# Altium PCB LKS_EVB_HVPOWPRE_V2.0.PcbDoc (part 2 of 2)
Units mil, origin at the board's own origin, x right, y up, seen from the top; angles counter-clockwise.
Board outline 6702.91 x 4340.71 mil, 2 copper layers (Top Layer, Bottom Layer); 149 components, 99 nets, 418 pads, 120 vias.
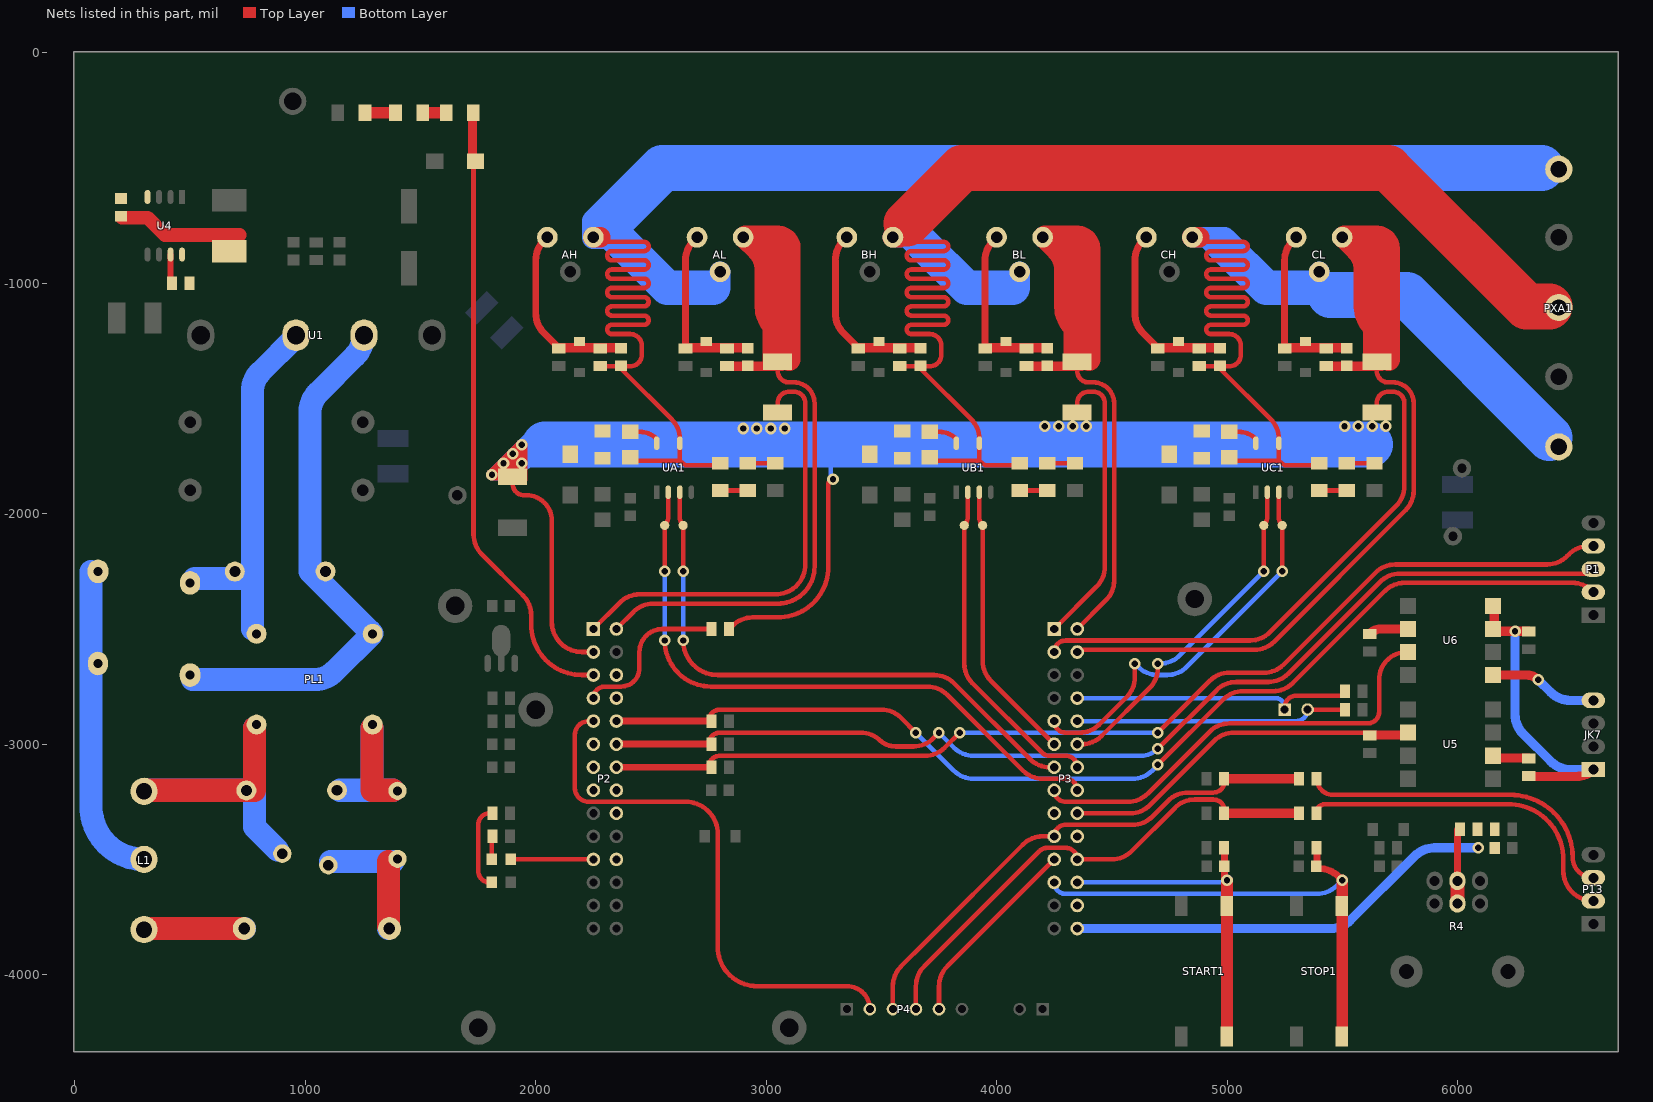
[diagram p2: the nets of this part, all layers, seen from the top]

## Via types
v1: diameter 50, hole 28, Top Layer to Bottom Layer, 120 vias

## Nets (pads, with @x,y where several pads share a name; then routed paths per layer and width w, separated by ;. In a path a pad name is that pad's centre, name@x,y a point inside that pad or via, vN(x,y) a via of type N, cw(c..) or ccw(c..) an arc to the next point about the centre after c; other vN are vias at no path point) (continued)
HA: P1.4 P2.21 R53.1 | length 4604.3
  Top Layer w20: R53.1@2750,-3100 cw(c2800,-3100) 2760,-3070 cw(c2800,-3100) 2770,-3060 cw(c2800,-3100) 2800,-3050 3690,-3050 ccw(c3690,-2929.29) 3775.36,-3014.64 v1(3840,-2950) ; v1(4700,-2950) 4924.64,-2725.36 cw(c5010,-2810.71) 5010,-2690 5160,-2690 ccw(c5160,-2569.29) 5245.36,-2654.64 5644.64,-2255.36 cw(c5730,-2340.71) 5730,-2220 6390,-2220 ccw(c6390,-2099.29) 6475.36,-2184.64 6484.64,-2175.36 cw(c6570,-2260.71) 6570,-2140 P1.4@6590,-2140
  Top Layer w30: P2.21@2350,-3100 R53.1@2750,-3100
  Bottom Layer w20: v1@3850,-2950 v1(4700,-2950)
HALL_A: P2.6
HALL_B: P2.7
HALL_C: P2.8
HB: P1.3 P2.20 R52.1 | length 4654.5
  Top Layer w20: R52.1@2750,-3000 cw(c2800,-3000) 2760,-2970 cw(c2800,-3000) 2770,-2960 cw(c2800,-3000) 2800,-2950 3410,-2950 cw(c3410,-3070.71) 3495.36,-2985.36 ; 3490,-2980 ccw(c3562.43,-2907.57) 3562.43,-3010 3640,-3010 ccw(c3640,-2889.29) 3725.36,-2974.64 v1(3750,-2950) ; v1(4700,-3020) 4954.64,-2765.36 cw(c5040,-2850.71) 5040,-2730 5180,-2730 ccw(c5180,-2609.29) 5265.36,-2694.64 5664.64,-2295.36 cw(c5750,-2380.71) 5750,-2260 P1.3@6590,-2260
  Top Layer w30: P2.20@2350,-3000 R52.1@2750,-3000
  Bottom Layer w20: v1(3750,-2950) 3814.64,-3014.64 ccw(c3900,-2929.29) 3900,-3050 4627.57,-3050 ccw(c4627.57,-2947.57) v1(4700,-3020)
HC: P1.2 P2.19 R51.1 | length 4718.5
  Top Layer w20: R51.1@2750,-2900 cw(c2800,-2900) 2760,-2870 cw(c2800,-2900) 2770,-2860 cw(c2800,-2900) 2800,-2850 3500,-2850 cw(c3500,-2970.71) 3585.36,-2885.36 v1(3650,-2950) ; v1(4700,-3090) 4984.64,-2805.36 cw(c5070,-2890.71) 5070,-2770 5200,-2770 ccw(c5200,-2649.29) 5285.36,-2734.64 5684.64,-2335.36 cw(c5770,-2420.71) 5770,-2300 6500,-2300 cw(c6500,-2420.71) P1.2@6585.36,-2335.36
  Top Layer w30: P2.19@2350,-2900 R51.1@2750,-2900
  Bottom Layer w20: v1(3650,-2950) 3814.64,-3114.64 ccw(c3900,-3029.29) 3900,-3150 4590,-3150 ccw(c4590,-3029.29) 4675.36,-3114.64 v1(4700,-3090)
HGND: JK7.4 U6.5 | length 467.4
  Top Layer w40: U6.5@6160,-2700 6301.72,-2700 cw(c6301.72,-2768.28) v1(6350,-2720)
  Bottom Layer w40: v1(6350,-2720) 6404.64,-2774.64 ccw(c6490,-2689.29) 6490,-2810 JK7.4@6590,-2810
IIC_CLK: P3.19 P6.2 R5.1 | length 1188.9
  Top Layer w20: P6.2@5350,-2850 R5.1@5510,-2850
  Bottom Layer w20: P3.19@4350,-2900 5300,-2900 ; 5300.25,-2899.75 cw(c5300,-2899.75) 5300,-2900 ; P6.2@5350,-2850 cw(c5300,-2850) 5300,-2900
IIC_DA: P3.18 P6.1 R6.1 | length 1236.4
  Top Layer w20: P6.1@5250,-2850 5250,-2840 cw(c5300,-2840) 5300,-2790 R6.1@5515,-2790
  Bottom Layer w20: P3.18@4350,-2800 5210,-2800 cw(c5210,-2840) 5250,-2840 P6.1@5250,-2850
L: F1.1 L1.3 | length 855
  Top Layer w100: L1.3@310,-3800 F1.1@730,-3800
  Bottom Layer w100: L1.3@300,-3800 F1.1@735,-3800
N: CX1.1 L1.1 PL1.1 RV1.1 | length 1761.4
  Top Layer w100: L1.1@300,-3200 780,-3200 PL1.1@780,-2930
  Bottom Layer w100: L1.1@300,-3200 CX1.1@740,-3200 ; PL1.1@780,-2930 780,-3360 RV1.1@880,-3460
NetCX4_1: CX4.1 U4.4
NetD4_K: D4.K R3P.1
NetD11_K: D11.K R1P.1
NetD21_K: D21.K R2P.1
NetDA2_1: AL.1 C11.1 DA2.1 K-A1.1 R31.1 | length 755.5
  Top Layer w30: K-A1.1@2650,-1280 2650,-900 cw(c2770.71,-900) 2685.36,-814.64 AL.1@2700,-800
  Top Layer w40: K-A1.1@2650,-1280 C11.1@2910,-1280
NetDA5_1: C24.1 CH.1 DA5.1 K+C1.2 R50.2 | length 801.7
  Top Layer w30: CH.1@4650,-800 4635.36,-814.64 ccw(c4720.71,-900) 4600,-900 4600,-1130 ccw(c4720.71,-1130) 4635.36,-1215.36 K+C1.2@4700,-1280
  Top Layer w40: K+C1.2@4700,-1280 C24.1@4970,-1280
NetDA6_1: C34.1 CL.1 DA6.1 K_C1.1 R63.1 | length 755.5
  Top Layer w30: K_C1.1@5250,-1280 5250,-900 cw(c5370.71,-900) 5285.36,-814.64 CL.1@5300,-800
  Top Layer w40: K_C1.1@5250,-1280 C34.1@5510,-1280
NetF1_2: F1.2 R26.2 RV1.2 | length 840
  Top Layer w100: F1.2@1360,-3790 1360,-3510
  Bottom Layer w100: RV1.2@1110,-3510 R26.2@1380,-3510 ; F1.2@1360,-3800 1360,-3510
NetK+A1_2: AH.1 C7.1 DA1.1 K+A1.2 R21.2 | length 801.7
  Top Layer w30: AH.1@2050,-800 2035.36,-814.64 ccw(c2120.71,-900) 2000,-900 2000,-1130 ccw(c2120.71,-1130) 2035.36,-1215.36 K+A1.2@2100,-1280
  Top Layer w40: K+A1.2@2100,-1280 C7.1@2370,-1280
NetK+B1_2: BH.1 C16.1 DA3.1 K+B1.2 R39.2 | length 801.7
  Top Layer w30: BH.1@3350,-800 3335.36,-814.64 ccw(c3420.71,-900) 3300,-900 3300,-1130 ccw(c3420.71,-1130) 3335.36,-1215.36 K+B1.2@3400,-1280
  Top Layer w40: K+B1.2@3400,-1280 C16.1@3670,-1280
NetK_B1_1: BL.1 C20.1 DA4.1 K_B1.1 R45.1 | length 755.5
  Top Layer w30: K_B1.1@3950,-1280 3950,-900 cw(c4070.71,-900) 3985.36,-814.64 BL.1@4000,-800
  Top Layer w40: K_B1.1@3950,-1280 C20.1@4210,-1280
NetLED3_1: LED3.1 R0.1 | length 99
  Top Layer w20: LED3.1@1809,-3500 R0.1@1809,-3401
NetLED_POWER_1: LED_POWER.1 R65.2 | length 376.1
  Top Layer w20: LED_POWER.1@1809,-3600 1800,-3600 cw(c1800,-3550) 1750,-3550 1750,-3350 cw(c1800,-3350) 1800,-3300 R65.2@1810,-3300
NetPL1_2: CX6.1 CY1.2 PL1.2 U1.1 | length 1583.5
  Bottom Layer w100: CY1.2@520,-2280 760,-2280 ; PL1.2@770,-2500 770,-1470 cw(c890.71,-1470) 805.36,-1384.64 U1.1@960,-1230
NetPL1_3: CX6.2 CY2.1 PL1.3 U1.3 | length 2340.2
  Bottom Layer w100: CY2.1@510,-2720 1040,-2720 ccw(c1040,-2599.29) 1125.36,-2684.64 PL1.3@1290,-2520 ; U1.3@1250,-1220 1250,-1230 cw(c1129.29,-1230) 1214.64,-1315.36 1055.36,-1474.64 ccw(c1140.71,-1560) 1020,-1560 1020,-2250 PL1.3@1280,-2510
NetR1_2: R1.2 R23.1 | length 120
  Top Layer w20: R23.1@2800,-1899.06 R1.2@2920,-1899.06
NetR1P_2: CAH1.1 R1P.2 UA1.8 | length 141.8
  Top Layer w20: CAH1.1@2410,-1644.88 2452.29,-1644.88 cw(c2452.29,-1747.71) 2505.96,-1660 cw(c2452.29,-1747.71) 2524.97,-1674.97 UA1.8@2525,-1693.7
NetR2_2: R2.2 R24.1 | length 120
  Top Layer w20: R24.1@4100,-1899.06 R2.2@4220,-1899.06
NetR2P_2: CBH1.1 R2P.2 UB1.8 | length 141.7
  Top Layer w20: CBH1.1@3710,-1644.88 3752.29,-1644.88 cw(c3752.29,-1747.71) 3805.96,-1660 cw(c3752.29,-1747.71) 3824.97,-1674.97 UB1.8@3825,-1693.7
NetR3_2: R3.2 R25.1 | length 120
  Top Layer w20: R25.1@5400,-1899.06 R3.2@5520,-1899.06
NetR3P_2: CCH1.1 R3P.2 UC1.8 | length 141.7
  Top Layer w20: CCH1.1@5010,-1644.88 5052.29,-1644.88 cw(c5052.29,-1747.71) 5105.96,-1660 cw(c5052.29,-1747.71) 5124.97,-1674.97 UC1.8@5125,-1693.7
NetR9_2: P13.2 R9.2 | length 1499.7
  Top Layer w20: R9.2@5380,-3310 cw(c5430,-3310) 5430,-3260 6220,-3260 cw(c6220,-3500) 6460,-3500 6460,-3550 ccw(c6590,-3550) P13.2@6590,-3680
NetR12_2: P13.3 R12.2 | length 1445.4
  Top Layer w20: R12.2@5390,-3150 ccw(c5460,-3150) 5460,-3220 6230,-3220 cw(c6230,-3490) 6500,-3490 ccw(c6590,-3490) P13.3@6590,-3580
NetR22_2: R22.2 R74.1 | length 120
  Top Layer w50: R22.2@1265,-260 R74.1@1385,-260
NetR26_1: CX1.2 PL1.4 R26.1 | length 860
  Top Layer w100: PL1.4@1290,-2930 1290,-3200 R26.1@1380,-3200
  Bottom Layer w100: CX1.2@1150,-3200 R26.1@1380,-3200 ; 1290,-3200 PL1.4@1290,-2930
NetR27_1: R27.1 U6.2 | length 165.3
  Top Layer w40: R27.1@5620,-2520 cw(c5668.28,-2568.28) 5668.28,-2500 U6.2@5780,-2500
NetR29_2: R29.2 U5.2 | length 150
  Top Layer w40: U5.2@6160,-3060 R29.2@6310,-3060
NetR55_2: R1.1 R55.2 | length 120
  Top Layer w20: R1.1@2920,-1780.94 R55.2@3040,-1780.94
NetR59_2: R2.1 R59.2 | length 120
  Top Layer w20: R2.1@4220,-1780.94 R59.2@4340,-1780.94
NetR61_2: R3.1 R61.2 | length 120
  Top Layer w20: R3.1@5520,-1780.94 R61.2@5640,-1780.94
NetR74_2: R74.2 R75.1 | length 100
  Top Layer w50: R74.2@1510,-260 R75.1@1610,-260
NetRX3_1: RX3.1 U4.7 | length 125
  Top Layer w25: RX3.1@415,-1000 U4.7@415,-875
NetRX3_2: CX4.2 L11.1 RX3.2 U4.8 | length 541.1
  Top Layer w60: CX4.2@205,-715 315,-715 390,-790 715,-790
NRST: P2.23
OC: P2.4 R8.2 | length 711.3
  Top Layer w20: P2.4@2250,-2800 cw(c2300,-2800) 2300,-2750 2370,-2750 ccw(c2370,-2670) 2450,-2670 2450,-2600 cw(c2550,-2600) 2550,-2500 R8.2@2760,-2500
P0.0: P2.22
P0.3: LED3.2 P2.11 | length 359
  Top Layer w20: LED3.2@1891,-3500 P2.11@2250,-3500
P0.4: P3.27
P1.3: P3.24
P2.1: P2.18
P2.7: P3.9
P2.10: P2.17
P3.2: P2.25
PE: CY1.1 CY2.2 L1.2 | length 1381.3
  Bottom Layer w100: CY1.1@70,-2250 70,-3270 ccw(c300,-3270) L1.2@300,-3500
RXD0/SPI_D1: P3.25 P4.4 R01.1 R9.1 | length 2191.5
  Top Layer w20: P4.4@3650,-4150 3650,-4050 cw(c3770.71,-4050) 3685.36,-3964.64 3790,-3860 ; 3785.36,-3864.64 4185.86,-3464.14 cw(c4220,-3498.28) 4220,-3450 4300,-3450 cw(c4300,-3500) P3.25@4350,-3500 4500,-3500 ccw(c4500,-3379.29) 4585.36,-3464.64 4774.64,-3275.36 cw(c4860,-3360.71) 4860,-3240 4940,-3240 cw(c4940,-3290) 4983.1,-3264.65 cw(c4940,-3290) R01.1@4990,-3290
  Top Layer w40: R01.1@4990,-3300 R9.1@5310,-3300
RXD1: P3.23 R28.1 U5.6 | length 1564.6
  Top Layer w20: P3.23@4350,-3300 4580,-3300 ccw(c4580,-3179.29) 4665.36,-3264.64 4944.64,-2985.36 cw(c5030,-3070.71) 5030,-2950 R28.1@5620,-2950
  Top Layer w40: R28.1@5620,-2960 U5.6@5780,-2960
SHUNT: P2.1 P2.2 P3.1 P3.2 R8.1 R15.2 R16.2 R17.2 R69.1 | length 12858.5
  Top Layer w20: R69.1@1900,-1840 1900,-1870 ccw(c1950,-1870) 1950,-1920 1960,-1920 cw(c1960,-2030) 2070,-2030 2070,-2470 ccw(c2200,-2470) 2200,-2600 P2.2@2250,-2600 ; P2.1@2250,-2500 2364.64,-2385.36 cw(c2450,-2470.71) 2450,-2350 3040,-2350 ccw(c3040,-2220) 3170,-2220 3170,-1520 ccw(c3120,-1520) 3120,-1470 3100,-1470 ccw(c3100,-1520) 3050,-1520 R15.2@3050,-1550 ; R8.1@2840,-2500 2854.64,-2485.36 cw(c2940,-2570.71) 2940,-2450 3060,-2450 ; 3050,-2450 ccw(c3050,-2230) 3270,-2230 3270,-1874.14 cw(c3304.14,-1874.14) v1@3280,-1850 ; P3.2@4250,-2600 cw(c4300,-2600) 4300,-2550 5100,-2550 ccw(c5100,-2429.29) 5185.36,-2514.64 5734.64,-1965.36 ccw(c5649.29,-1880) 5770,-1880 5770,-1520 ccw(c5720,-1520) 5720,-1470 5700,-1470 ccw(c5700,-1520) 5650,-1520 R17.2@5650,-1550 ; P3.1@4250,-2500 4434.64,-2315.36 ccw(c4349.29,-2230) 4470,-2230 4470,-1520 ; R16.2@4350,-1550 4350,-1520 ; 4350,-1520 cw(c4400,-1520) 4400,-1470 ; 4350,-1520 cw(c4400,-1520) 4400,-1470 ; 4400,-1470 4420,-1470 ; 4400,-1470 4420,-1470 ; 4420,-1470 cw(c4420,-1520) 4470,-1520 ; 4420,-1470 cw(c4420,-1520) 4470,-1520
  Top Layer w50: R69.1@1870,-1820 v1@1930,-1760 ; R69.1@1930,-1830 v1(1810,-1830) v1(1940,-1700) R69.1@1940,-1850
  Bottom Layer w20: v1@3280,-1850 3280,-1778.28
  Bottom Layer w40: v1@1960,-1780 2060,-1780
  Bottom Layer w50: 1880,-1820 1960,-1740 ; v1@1960,-1780 1910,-1830 v1(1810,-1830) 1990,-1650
  Bottom Layer w200: 2040,-1700 2370,-1700 ; 2110,-1700 5620,-1700
  other v1: 3290,-1850 1860,-1780 1940,-1780 1900,-1740 2900,-1630 2960,-1630 3020,-1630 3080,-1630 4210,-1620 4270,-1620 4330,-1620 4390,-1620 5510,-1620 5570,-1620 5630,-1620 5690,-1620
SHUNT_U: AL.3 C11.2 P2.15 R15.1 R31.2 | length 3794
  Top Layer w20: P2.15@2350,-2500 2424.64,-2425.36 cw(c2510,-2510.71) 2510,-2390 ; 2500,-2390 3050,-2390 ccw(c3050,-2230) 3210,-2230 3210,-1520 ccw(c3120,-1520) 3120,-1430 3100,-1430 cw(c3100,-1380) 3050,-1380 R15.1@3050,-1339.76
  Top Layer w40: R31.2@2830,-1360 R15.1@3070,-1360
  Top Layer w50: AL.3@2900,-800 AL.3@2914.64,-814.64
  Top Layer w100: R15.1@3035,-1331 3035,-1195 ; 3035.36,-1185.36 cw(c3120.71,-1100) 3000,-1100 3000,-940 ccw(c2879.29,-940) 2964.64,-854.64 2910,-800 3050,-800 cw(c3050,-850) 3100,-850 R15.1@3100,-1330 ; 3040,-1140 3040,-860
SHUNT_V: BL.3 C20.2 P3.15 R16.1 R45.2 | length 3178.4
  Top Layer w20: P3.15@4350,-2500 4474.64,-2375.36 ccw(c4389.29,-2290) 4510,-2290 4510,-1520 ccw(c4420,-1520) 4420,-1430 4400,-1430 cw(c4400,-1380) 4350,-1380 R16.1@4350,-1339.76
  Top Layer w40: R45.2@4130,-1360 R16.1@4370,-1360
  Top Layer w50: BL.3@4200,-800 BL.3@4214.64,-814.64
  Top Layer w100: 4335.36,-1185.36 cw(c4420.71,-1100) 4300,-1100 4300,-940 ccw(c4179.29,-940) 4264.64,-854.64 4210,-800 4350,-800 cw(c4350,-850) 4400,-850 R16.1@4400,-1330 ; R16.1@4340,-1331 4340,-1140 4340,-860
SHUNT_W: C34.2 CL.3 P3.16 R17.1 R63.2 | length 4261
  Top Layer w20: P3.16@4350,-2590 5120,-2590 ccw(c5120,-2469.29) 5205.36,-2554.64 5774.64,-1985.36 ccw(c5689.29,-1900) 5810,-1900 5810,-1520 ccw(c5720,-1520) 5720,-1430 5700,-1430 cw(c5700,-1380) 5650,-1380 R17.1@5650,-1339.76
  Top Layer w40: R63.2@5430,-1360 R17.1@5670,-1360
  Top Layer w50: CL.3@5500,-800 CL.3@5514.64,-814.64
  Top Layer w100: 5635.36,-1185.36 cw(c5720.71,-1100) 5600,-1100 5600,-940 ccw(c5479.29,-940) 5564.64,-854.64 5510,-800 5650,-800 cw(c5650,-850) 5700,-850 R17.1@5700,-1330 ; R17.1@5640,-1330 5640,-1160 ; 5640,-1140 5640,-860
SPI_CLK: P3.11 P4.5 | length 858.5
  Top Layer w20: P4.5@3750,-4150 3750,-4050 cw(c3870.71,-4050) 3785.36,-3964.64 3890,-3860 ; 3885.36,-3864.64 P3.11@4250,-3500
SPI_CS: P2.5 P4.2 | length 2382.5
  Top Layer w20: P2.5@2250,-2900 2230,-2900 ccw(c2230,-2960) 2170,-2960 2170,-3190 ccw(c2230,-3190) 2230,-3250 2400,-3250 2650,-3250 cw(c2650,-3390) 2790,-3390 2790,-3880 ccw(c2960,-3880) 2960,-4050 3350,-4050 cw(c3350,-4150) P4.2@3450,-4150
SPIN: C19.2 P3.28 R42.2 R43.2 | length 1874.6
  Bottom Layer w40: P3.28@4350,-3800 5450,-3800 ccw(c5450,-3679.29) 5535.36,-3764.64 5814.64,-3485.36 cw(c5900,-3570.71) 5900,-3450 v1(6090,-3450)
START1: C311.2 P3.26 R7.2 START1.2 START1.4 | length 1486.8
  Top Layer w30: v1@4990,-3590 R7.2@4990,-3440
  Top Layer w50: START1.2@5000,-4270 v1(5000,-3590)
  Bottom Layer w20: P3.26@4350,-3600 v1@4980,-3600 ; 4975.86,-3600 ccw(c4975.86,-3565.86) v1(5000,-3590)
STOP1: C2.2 P3.12 R13.2 STOP1.2 STOP1.4 | length 2173
  Top Layer w30: C2.2@5390,-3540 R13.2@5390,-3440 ; C2.2@5400,-3540 cw(c5400,-3660.71) v1@5485.36,-3575.36
  Top Layer w50: STOP1.2@5500,-4270 v1(5500,-3590)
  Bottom Layer w20: P3.12@4250,-3600 ccw(c4300,-3600) 4300,-3650 5390,-3650 ccw(c5390,-3529.29) 5475.36,-3614.64 v1(5500,-3590)
TXD0/SPI_D2: P3.10 P4.3 R02.1 R12.1 | length 2259.4
  Top Layer w20: P4.3@3550,-4150 3550,-4050 cw(c3670.71,-4050) 3585.36,-3964.64 3690,-3860 ; 3685.36,-3864.64 4114.64,-3435.36 cw(c4200,-3520.71) 4200,-3400 P3.10@4250,-3400 cw(c4300,-3400) 4300,-3350 4590,-3350 ccw(c4590,-3229.29) 4675.36,-3314.64 4744.64,-3245.36 cw(c4830,-3330.71) 4830,-3210 4940,-3210 ccw(c4940,-3160) 4983.1,-3185.35 ccw(c4940,-3160) R02.1@4990,-3160
  Top Layer w40: R02.1@4990,-3150 R12.1@5310,-3150
TXD1: P3.8 U6.3 | length 1926
  Top Layer w20: P3.8@4250,-3200 ccw(c4300,-3200) 4300,-3250 4570,-3250 ccw(c4570,-3129.29) 4655.36,-3214.64 4924.64,-2945.36 cw(c5010,-3030.71) 5010,-2910 5610,-2910 ccw(c5610,-2860) 5660,-2860 5660,-2720 cw(c5780,-2720) U6.3@5780,-2600
U_N: P3.7 UA1.3 UN.1 | length 2506.3
  Top Layer w20: UA1.3@2625,-1906.3 2625,-2015.13 ccw(c2674.87,-2015.13) UN.1@2639.61,-2050.39 2639.61,-2249.61 ccw(c2640,-2249.61) v1(2640,-2250) ; v1(2640,-2550) ccw(c2790,-2550) 2790,-2700 3050,-2700 3730,-2700 cw(c3730,-2820.71) 3815.36,-2735.36 4150,-3070 ; 4144.64,-3064.64 ccw(c4230,-2979.29) 4230,-3100 P3.7@4250,-3100
  Bottom Layer w20: v1(2640,-2550) v1(2640,-2250)
U_P: P3.22 UA1.2 UP.1 | length 2736
  Top Layer w20: v1(2560,-2550) ccw(c2760,-2550) 2760,-2750 3700,-2750 cw(c3700,-2870.71) 3785.36,-2785.36 4114.64,-3114.64 ccw(c4200,-3029.29) 4200,-3150 4300,-3150 cw(c4300,-3200) P3.22@4350,-3200 ; v1(2560,-2250) cw(c2560,-2249.61) 2559.61,-2249.61 UP.1@2559.61,-2050.39 ccw(c2522.44,-2013.23) 2575,-2013.23 UA1.2@2575,-1906.3
  Bottom Layer w20: v1(2560,-2550) v1(2560,-2250)
UX: AH.3 AL.2 C7.2 CAH1.2 PXA1.1 R21.1 R23.2 UA1.6 | length 8554.7
  Top Layer w20: AH.3@2250,-820 2470,-820 cw(c2470,-840) 2470,-860 2330,-860 ccw(c2330,-880) 2330,-900 2470,-900 cw(c2470,-920) 2470,-940 2330,-940 ccw(c2330,-960) 2330,-980 2470,-980 cw(c2470,-1000) 2470,-1020 2330,-1020 ccw(c2330,-1040) 2330,-1060 2470,-1060 cw(c2470,-1080) 2470,-1100 2330,-1100 ccw(c2330,-1120) 2330,-1140 2470,-1140 cw(c2470,-1160) 2470,-1180 2330,-1180 ccw(c2330,-1200) 2330,-1220 2410,-1220 cw(c2410,-1270) 2460,-1270 2460,-1310 cw(c2410,-1310) 2410,-1360 C7.2@2370,-1360 ; R21.1@2280,-1360 C7.2@2365,-1360 ; C7.2@2370,-1370 C7.2@2370,-1358 ccw(c2398.97,-1358) 2370.07,-1360 ccw(c2398.97,-1358) 2378.49,-1378.49 2589.64,-1589.64 cw(c2504.29,-1675) 2625,-1675 2625,-1765 ; C7.2@2370,-1350 ccw(c2490.71,-1350) C7.2@2370.41,-1360 ; CAH1.2@2410,-1770 2625,-1770 2650,-1790 R23.2@2800,-1790
  Top Layer w90: AH.3@2250,-800 AH.3@2280,-800
  Bottom Layer w90: 2800,-1020 AL.2@2800,-950
  Bottom Layer w100: 2350,-800 AH.3@2250,-800 2250,-730 2350,-630
  Bottom Layer w150: 2320,-770 2570,-1020 2770,-1020
  Bottom Layer w200: 2310,-740 2550,-500 6364.72,-500
V_N: P3.6 UB1.3 VN.1 | length 1220.9
  Top Layer w20: UB1.3@3925,-1906.3 3925,-2015.13 ccw(c3974.87,-2015.13) VN.1@3939.61,-2050.39 cw(c3938.66,-2051.34) 3940,-2051.34 3940,-2640 ccw(c4060.71,-2640) 3975.36,-2725.36 P3.6@4250,-3000
V_P: P3.21 UB1.2 VP.1 | length 1454.2
  Top Layer w20: UB1.2@3875,-1906.3 3875,-2013.23 cw(c3822.44,-2013.23) VP.1@3859.61,-2050.39 cw(c3858.66,-2051.34) 3860,-2051.34 3860,-2650 ccw(c3980.71,-2650) 3895.36,-2735.36 4195.86,-3035.86 ccw(c4230,-3001.72) 4230,-3050 4300,-3050 cw(c4300,-3100) P3.21@4350,-3100
VCC1+5V: JK7.1 R28A.2 R29.1 U6.7 U6.8 | length 1349.8
  Top Layer w40: U6.7@6160,-2510 R28A.2@6310,-2510 ; U6.7@6160,-2490 U6.8@6160,-2390 ; R29.1@6310,-3140 6517.57,-3140 ccw(c6517.57,-3037.57) JK7.1@6590,-3110
  Bottom Layer w40: v1(6250,-2510) 6250,-2870 ccw(c6370.71,-2870) 6285.36,-2955.36 ; 6290,-2960 6404.64,-3074.64 ccw(c6490,-2989.29) 6490,-3110 JK7.1@6590,-3110
VOL_ADC: P2.3 R75.2 ZD1.K | length 2692.8
  Top Layer w20: ZD1.K@1730,-480 1730,-2090 ccw(c1850.71,-2090) 1735.05,-2124.56 ccw(c1850.71,-2090) 1765.36,-2175.36 1944.64,-2354.64 cw(c1859.29,-2440) 1980,-2440 1980,-2480 ccw(c2200,-2480) 2200,-2700 P2.3@2250,-2700
  Top Layer w40: ZD1.K@1725,-465 R75.2@1725,-260.94
VX: BH.3 BL.2 C16.2 CBH1.2 PXA1.3 R24.2 R39.1 UB1.6 | length 7615.3
  Top Layer w20: BH.3@3550,-820 3770,-820 cw(c3770,-840) 3770,-860 3630,-860 ccw(c3630,-880) 3630,-900 3770,-900 cw(c3770,-920) 3770,-940 3630,-940 ccw(c3630,-960) 3630,-980 3770,-980 cw(c3770,-1000) 3770,-1020 3630,-1020 ccw(c3630,-1040) 3630,-1060 3770,-1060 cw(c3770,-1080) 3770,-1100 3630,-1100 ccw(c3630,-1120) 3630,-1140 3770,-1140 cw(c3770,-1160) 3770,-1180 3630,-1180 ccw(c3630,-1200) 3630,-1220 3710,-1220 cw(c3710,-1270) 3760,-1270 3760,-1310 cw(c3710,-1310) 3710,-1360 C16.2@3676.82,-1360 ; R39.1@3580,-1360 C16.2@3665,-1360 ; C16.2@3670,-1370 C16.2@3670,-1358 ccw(c3698.97,-1358) 3670.07,-1360 ccw(c3698.97,-1358) 3678.49,-1378.49 3889.64,-1589.64 cw(c3804.29,-1675) 3925,-1675 3925,-1765 ; C16.2@3670,-1360 3670.41,-1360 cw(c3790.71,-1350) C16.2@3670,-1350 ; CBH1.2@3710,-1770 3925,-1770 3950,-1790 R24.2@4100,-1790
  Top Layer w90: BH.3@3550,-800 BH.3@3580,-800
  Top Layer w200: 3610,-740 3850,-500 5700,-500 6300,-1100 PXA1.3@6400,-1100
  Bottom Layer w90: BH.3@3550,-800 3690,-800 ; 3610,-800 3850,-1040 ; 4100,-1020 BL.2@4100,-950
  Bottom Layer w150: 3680,-830 3870,-1020 4070,-1020
W_N: P3.5 UC1.3 WN.1 | length 1741.3
  Top Layer w20: P3.5@4250,-2900 ccw(c4300,-2900) 4300,-2950 4360,-2950 ccw(c4360,-2829.29) 4445.36,-2914.64 4564.64,-2795.36 ccw(c4479.29,-2710) 4600,-2710 v1(4600,-2650) ; UC1.3@5225,-1906.3 5225,-2015.13 ccw(c5274.87,-2015.13) WN.1@5239.61,-2050.39 cw(c5238.66,-2051.34) 5240,-2051.34 v1(5240,-2250)
  Bottom Layer w20: v1(4600,-2650) 4614.64,-2664.64 ccw(c4700,-2579.29) 4700,-2700 4740,-2700 ccw(c4740,-2579.29) 4825.36,-2664.64 v1(5240,-2250)
W_P: P3.20 UC1.2 WP.1 | length 1474
  Top Layer w20: P3.20@4370,-3000 ccw(c4370,-2879.29) 4455.36,-2964.64 4664.64,-2755.36 ccw(c4579.29,-2670) 4700,-2670 v1(4700,-2650) ; v1(5160,-2250) 5160,-2051.34 ccw(c5158.66,-2051.34) WP.1@5159.61,-2050.39 ccw(c5122.44,-2013.23) 5175,-2013.23 UC1.2@5175,-1906.3
  Bottom Layer w20: v1(4700,-2650) 4710,-2650 ccw(c4710,-2529.29) 4795.36,-2614.64 v1(5160,-2250)
WX: C24.2 CCH1.2 CH.3 CL.2 PXA1.5 R25.2 R50.1 UC1.6 | length 5690.5
  Top Layer w20: CH.3@4850,-820 5070,-820 cw(c5070,-840) 5070,-860 4930,-860 ccw(c4930,-880) 4930,-900 5070,-900 cw(c5070,-920) 5070,-940 4930,-940 ccw(c4930,-960) 4930,-980 5070,-980 cw(c5070,-1000) 5070,-1020 4930,-1020 ccw(c4930,-1040) 4930,-1060 5070,-1060 cw(c5070,-1080) 5070,-1100 4930,-1100 ccw(c4930,-1120) 4930,-1140 5070,-1140 cw(c5070,-1160) 5070,-1180 4930,-1180 ccw(c4930,-1200) 4930,-1220 5010,-1220 cw(c5010,-1270) 5060,-1270 5060,-1310 cw(c5010,-1310) 5010,-1360 C24.2@4970,-1360 ; R50.1@4880,-1360 C24.2@4965,-1360 ; C24.2@4970,-1370 C24.2@4970,-1358 ccw(c4998.97,-1358) 4970.07,-1360 ccw(c4998.97,-1358) 4978.49,-1378.49 5189.64,-1589.64 cw(c5104.29,-1675) 5225,-1675 5225,-1765 ; C24.2@4970,-1350 ccw(c5090.71,-1350) C24.2@4970.41,-1360 ; CCH1.2@5010,-1770 5225,-1770 5250,-1790 R25.2@5400,-1790
  Top Layer w90: CH.3@4850,-800 CH.3@4880,-800
  Bottom Layer w90: CH.3@4850,-800 4990,-800 ; 4910,-800 5150,-1040 ; 5400,-1020 CL.2@5400,-950
  Bottom Layer w150: 4980,-830 5170,-1020 5370,-1020
  Bottom Layer w200: 5450,-1050 5780,-1050 PXA1.5@6400,-1670
ZB: R4.3 R4.5 R42.1 | length 381.6
  Top Layer w30: 6000,-3650 R42.1@6000,-3370
  Top Layer w60: R4.5@6000,-3690 R4.3@6000,-3588.42
pads on no net: PXA1.2 PXA1.4 R4.0 U4.3 U4.6 U5.1 U5.4 U6.1 U6.4
copper on no net: | length 15515.2
  Top Layer w10: 2301.49,-2612.13 cw(c2350,-2600) 2368.57,-2646.42 ; 5970,-3180 5970,-2390 cw(c6020,-2390) 6020,-2340 6400,-2340 cw(c6400,-2390) 6450,-2390 6450,-2490 ccw(c6500,-2490) 6500,-2540 6660,-2540 ; 6390.14,-4299.78 cw(c6496.06,-4133.86) 6409.11,-3957.26 ; 6404.9,-3959.39 cw(c6496.06,-4133.86) 6660.95,-4026.34 ; 6520,-3380 6660,-3380 ; 3496.85,-3600 ccw(c3300,-3600) 3496.85,-3600 ; 3796.85,-2450 ccw(c3600,-2450) 3796.85,-2450 ; 5879.53,-3986.85 ccw(c5779.53,-3986.85) 5879.53,-3986.85 ; 6320.47,-3986.85 ccw(c6220.47,-3986.85) 6320.47,-3986.85
  Bottom Layer w10: 1605,-2285 1985,-2285 1985,-2000 ; 6390.14,-4299.78 cw(c6496.06,-4133.86) 6398.81,-3962.71 ; 6395,-3964.93 cw(c6496.06,-4133.86) 6660.95,-4026.34 ; 6660,-3380 6520,-3380 5970,-3180 5970,-2390 cw(c6020,-2390) 6020,-2340 6400,-2340 cw(c6400,-2390) 6450,-2390 6450,-2490 ccw(c6500,-2490) 6500,-2540 6660,-2540 ; 393.7,-196.85 ccw(c196.85,-196.85) 393.7,-196.85 ; 2400,-2600 ccw(c2350,-2600) 2400,-2600 ; 3496.85,-3600 ccw(c3300,-3600) 3496.85,-3600 ; 3796.85,-2450 ccw(c3600,-2450) 3796.85,-2450 ; 5879.53,-3986.85 ccw(c5779.53,-3986.85) 5879.53,-3986.85 ; 6320.47,-3986.85 ccw(c6220.47,-3986.85) 6320.47,-3986.85

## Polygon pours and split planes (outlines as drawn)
GND on Top Layer "Top Layer-GND" (hatched 90Degree grid 10 track 10, remove dead copper, pour order 0): 1600,-2050 1650,-2050 1650,-2180 1850,-2380 1850,-2700 2400,-2700 2400,-2010 6690,-2010 6690,-4330 1600,-4330
GND on Top Layer "Top Layer-GND 1" (hatched 90Degree grid 10 track 10, remove dead copper, pour order 1): 2100,-2010 2405,-2010 2405,-2550 2100,-2550
GND on Top Layer "Top Layer-GND 2" (hatched 90Degree grid 10 track 10, remove dead copper, pour order 2): 1650,-440 0,-440 0,-720 420,-720 420,-1000 1650,-1000
GND on Top Layer "Top Layer-GND 3" (hatched 90Degree grid 10 track 10, remove dead copper, pour order 3): 6670,-1980 6530,-1980 6410,-2050 6670,-2050
GND on Top Layer "Top Layer-GND 4" (hatched 90Degree grid 10 track 10, remove dead copper, pour order 4): 1560,-1070 1560,-2150 1670,-2150 1670,-1090
GND on Bottom Layer "Bottom Layer-GND" (hatched 90Degree grid 10 track 10, remove dead copper, pour order 5): 1650,-1000 1650,-440 730,-440 540,-630 540,-1000
GND on Bottom Layer "Bottom Layer-GND 1" (hatched 90Degree grid 10 track 10, remove dead copper, pour order 6): 390,-1070 390,-840 540,-690 540,-980
GND on Bottom Layer "Bottom Layer-GND 2" (hatched 90Degree grid 10 track 10, remove dead copper, pour order 7): 1600,-2010 6690,-2010 6690,-4330 1600,-4330

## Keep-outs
Keep-Out Layer:
  circle w10: c6496.06,-4133.86 r59.05
  circle w10: c6496.06,-196.85 r59.05
  circle w10: c196.85,-196.85 r59.05
  circle w10: c1048.02,-560.53 r196.85
  circle w10: c3600,-2450 r59.05
  circle w10: c3300,-3600 r59.05
  circle w10: c196.85,-4133.86 r59.06
  rectangle net GND: 1380,-2040 1460,-1950
  lines w10: 6642.91,0 cw(c6642.91,-50) 6692.91,-50 6692.91,-4280.71 cw(c6642.91,-4280.71) 6642.91,-4330.71 50,-4330.71 cw(c50,-4280.71) 0,-4280.71 0,-50 cw(c50,-50) 50,0 1670,0 cw(c1670,-120.71) 1755.36,-35.36 2034.64,-314.64 ; 2034.64,-314.64 ccw(c2120,-229.29) 2120,-350 ; 2034.64,-314.64 ccw(c2120,-229.29) 2120,-350 ; 2120,-350 5430,-350 ccw(c5430,-229.29) 5515.36,-314.64 5794.64,-35.36 cw(c5880,-120.71) 5880,0 ; 5880,0 6640,0 5880,0
  lines w20: 6100,-3180 6210,-3180 ; 6100,-2340 6210,-2340 ; 6260,-3185 6370,-3195
  lines w30: 305,-790 350,-835 ; 1780,-1200 1870,-1110
  lines w50: 200,-3300 200,-3110 ; 260,-1235 260,-1060 ; 690,-2820 890,-2820 ; 690,-2610 880,-2610 ; 1000,-3560 1000,-3440 ; 1120,-2150 1210,-2240 ; 1290,-1750 1450,-1750 ; 1380,-3010 1380,-2830 ; 1380,-2620 1380,-2430 ; 1460,-3870 1460,-3730 ; 1480,-3590 1480,-3110 ; 5910,-1950 6090,-1950 ; 6300,-360 6430,-360 6560,-490 ; 6311.21,-1381.21 6460,-1530
Mechanical 1:
  lines w5: 0,-4097.96 0,-3655.61 0,-2084.61

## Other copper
Top Layer:
  rectangle net +15V: 1900,-2920 2000,-2780
  rectangle net GND: 1870,-2190 1920,-2130
  rectangle net GND: 1830,-2140 1920,-2090
  rectangle net GND: 3500,-2090 3800,-1990
  rectangle net SHUNT: 4180,-1650 4413,-1525
  rectangle net +15V: 3415,-1950 3830,-1880
  rectangle net GND: 2190,-2090 2480,-1990
  rectangle net SHUNT: 2870,-1660 3113,-1530
  rectangle net +15V: 2120,-1950 2530,-1880
  rectangle net +15V: 1295,-740 1485,-590
  rectangle net +15V: 595,-690 800,-590
  rectangle net NetCX4_1: 175,-655.53 318.02,-595
  rectangle net +310V: 150,-905 315,-845
  rectangle net NetRX3_2: 465,-910 745,-790
  rectangle net NetRX3_2: 475,-1030 520,-880
  rectangle net GND: 1525,-535 1595,-470
  rectangle net GND: 455,-655 575,-595
  rectangle net NetR1P_2: 2255,-1665 2445,-1615
  rectangle net NetD11_K: 2120,-1780 2320,-1730
  rectangle net NetR2P_2: 3555,-1665 3745,-1615
  rectangle net NetD21_K: 3420,-1780 3645,-1730
  rectangle net GND: 4790,-2090 5080,-1990
  rectangle net SHUNT: 5480,-1650 5713,-1525
  rectangle net +15V: 4715,-1950 5130,-1880
  rectangle net NetD4_K: 4720,-1780 4945,-1730
  rectangle net NetR3P_2: 4875,-1665 5065,-1615
  rectangle net SPIN: 6070,-3470 6180,-3350
Bottom Layer:
  rectangle net +310V: 1915,-1225 2055,-1180
  rectangle net GND: 1700,-1120 1760,-1020
  rectangle net GND: 1650,-1140 1710,-960
  rectangle net +310V: 1880,-1260 2070,-1220
  rectangle net +310V: 5930,-1910 6070,-1650
  rectangle net GND: 1320,-1960 1450,-1790
  rectangle net GND: 5270,-2100 5410,-2000
  rectangle net GND: 1290,-2130 1400,-1940
  rectangle net GND: 1390,-2190 1600,-2010

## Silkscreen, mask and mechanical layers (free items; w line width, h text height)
Top Overlay:
  drawing of 457 lines, arcs and shapes, not listed
  text "HVDE" at 940,-130 h90
  text "U" at 2410,-600 h180
  text "V" at 3710,-600 h180
  text "W" at 4990,-600 h180
  text "U" at 5980,-600 h180
  text "V" at 5980,-1200 h180
  text "W" at 5940,-1680 h180
  text "15V" at 1630,-1850 h40
  text "5VH" at 6327.95,-2054.82 h40
  text "HA" at 6327.95,-2162 h40
  text "HB" at 6327.95,-2262.33 h40
  text "GND" at 1430,-2290 h120
  text "HC" at 6327.95,-2361.11 h40
  text "SHUNT_U" at 2410,-2410 h36
  text "GND" at 4970,-2420 h90
  text "GND" at 6270,-2450 h40
  text "SHUNT_V" at 4410,-2510 h36
  text "2N" at 2100,-2520 h50
  text "2P" at 2420,-2520 h50
  text "SHUNT_W" at 4410,-2600 h36
  text "3P" at 2100,-2620 h50
  text "3N" at 2420,-2620 h50
  text "VOL" at 2060,-2720 h50
  text "BEMF_V" at 4000,-2720 h36
  text "BEMF_W" at 4410,-2720 h36
  text "SPI_DO" at 2420,-2730 h50
  text "SPI_CS" at 2030,-2740 h50 r90
  text "IIC_DA" at 5280,-2780 h60 r90
  text "IIC_CLK" at 5380,-2780 h60 r90
  text "G" at 6400,-2810 h36
  text "OC" at 2100,-2820 h50
  text "BEMF_U" at 4000,-2820 h36
  text "TXD1" at 6320,-2890 h36
  text "HC" at 2410,-2930 h36
  text "RXD1" at 6330,-2930 h36 r315
  text "HB" at 2410,-3020 h36
  text "HA" at 2410,-3120 h36
  text "5V" at 6370,-3180 h36
  text "N" at 570,-3250 h90
  text "+15V" at 2070,-3370 h120 r90
  text "SPI_DI" at 3990,-3430 h50
  text "GND" at 6330,-3500 h40
  text "SPI_CLK" at 3920,-3530 h50
  text "TXD" at 6330,-3600 h40
  text "RXD" at 6330,-3700 h40
  text "220~" at 700,-3710 h120 r90
  text "L" at 570,-3860 h90
  text "+5V" at 6320,-3860 h40
  text "GND" at 3380,-4070 h60 r90
  text "SPI_CS" at 3480,-4070 h60 r90
  text "SPI_D2" at 3580,-4070 h60 r90
  text "SPI_D1" at 3680,-4070 h60 r90
  text "SPI_CLK" at 3780,-4070 h60 r90
  text "5V" at 3880,-4070 h60 r90
  text "CAN_RX" at 4270,-4070 h60
  text "GND" at 1630,-4130 h120
  text "CAN_TX" at 4270,-4180 h60
  text "LKS_DEMO_HV_V7.3_20211220" at 250,-4280 h60
  text "+5V" at 2670,-4290 h120
Bottom Overlay:
  drawing of 445 lines, arcs and shapes, not listed
Top Solder:
  circle w78.74: c943.49,-4079.04 r17.13
Mechanical 1:
  circle w10: c6496.06,-4133.86 r59.05
  circle w10: c6496.06,-196.85 r59.05
  circle w10: c196.85,-196.85 r59.05
  circle w10: c1048.02,-560.53 r196.85
  circle w10: c3600,-2450 r59.05
  circle w10: c3300,-3600 r59.05
  circle w10: c196.85,-4133.86 r59.06
  lines w10: -50,0 50,0 ; 0,-40 0,40 ; 6640,0 5880,0 ccw(c5880,-120.71) 5794.64,-35.36 5515.36,-314.64 cw(c5430,-229.29) 5430,-350 2120,-350 cw(c2120,-229.29) 2034.64,-314.64 1755.36,-35.36 ccw(c1670,-120.71) 1670,0 50,0 ; 6642.91,0 cw(c6642.91,-50) 6692.91,-50 6692.91,-4280.71 cw(c6642.91,-4280.71) 6642.91,-4330.71 50,-4330.71 cw(c50,-4280.71) 0,-4280.71 0,-50 cw(c50,-50) 50,0
  lines w20: 6100,-3180 6210,-3180 ; 6100,-2340 6210,-2340 ; 6260,-3185 6370,-3195
  lines w30: 305,-790 350,-835 ; 1780,-1200 1870,-1110
  lines w50: 200,-3300 200,-3110 ; 260,-1235 260,-1060 ; 690,-2820 890,-2820 ; 690,-2610 880,-2610 ; 1000,-3560 1000,-3440 ; 1120,-2150 1210,-2240 ; 1290,-1750 1450,-1750 ; 1380,-3010 1380,-2830 ; 1380,-2620 1380,-2430 ; 1460,-3870 1460,-3730 ; 1480,-3590 1480,-3110 ; 5910,-1950 6090,-1950 ; 6300,-360 6430,-360 6560,-490 ; 6311.21,-1381.21 6460,-1530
